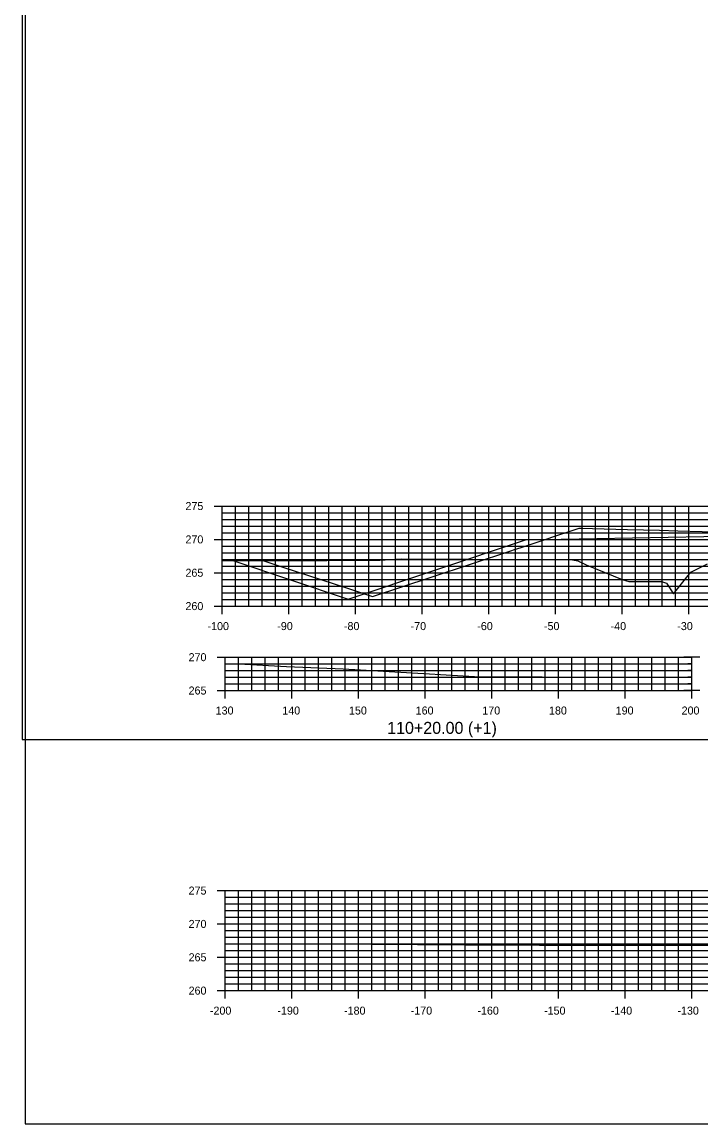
# Model space of a CAD drawing. Extents: x 1661012 to 1662122, y 670053 to 671852.
# Drawn here: x 1661677 to 1661778.9, y 671480 to 671645.2 of the extents above; entities that cross this region are included whole.
import ezdxf

# ---------------------------------------------------------------- set-up
doc = ezdxf.new("R2010")
doc.units = 0
for name, color, linetype in [('R_Concrete', 7, 'Continuous'), ('R_Concrete Hidden', 7, 'Continuous'), ('R_Erosion', 7, 'Continuous'), ('R_Exist Surface', 7, 'Continuous'), ('R_Proposed Road', 7, 'Continuous'), ('R_ROW Annot', 7, 'Continuous')]:
    doc.layers.add(name, color=color, linetype=linetype)

msp = doc.modelspace()

# ---------------------------------------------------------------- linework, layer by layer
at = {"layer": 'R_Concrete'}
for p, q in [((1661705.82, 671572.62), (1661708.22, 671572.62)), ((1661707.02, 671572.62), (1661907.02, 671572.62)), ((1661707.02, 671557.62), (1661707.02, 671572.62)), ((1661707.02, 671557.62), (1661707.02, 671572.62)), ((1661709.02, 671557.62), (1661709.02, 671572.62)), ((1661711.02, 671557.62), (1661711.02, 671572.62)), ((1661713.02, 671557.62), (1661713.02, 671572.62)), ((1661715.02, 671557.62), (1661715.02, 671572.62)), ((1661717.02, 671557.62), (1661717.02, 671572.62)), ((1661719.02, 671557.62), (1661719.02, 671572.62)), ((1661721.02, 671557.62), (1661721.02, 671572.62)), ((1661723.02, 671557.62), (1661723.02, 671572.62)), ((1661725.02, 671557.62), (1661725.02, 671572.62)), ((1661727.02, 671557.62), (1661727.02, 671572.62)), ((1661729.02, 671557.62), (1661729.02, 671572.62)), ((1661731.02, 671557.62), (1661731.02, 671572.62)), ((1661733.02, 671557.62), (1661733.02, 671572.62)), ((1661735.02, 671557.62), (1661735.02, 671572.62)), ((1661737.02, 671557.62), (1661737.02, 671572.62)), ((1661739.02, 671557.62), (1661739.02, 671572.62)), ((1661741.02, 671557.62), (1661741.02, 671572.62)), ((1661743.02, 671557.62), (1661743.02, 671572.62)), ((1661745.02, 671557.62), (1661745.02, 671572.62)), ((1661747.02, 671557.62), (1661747.02, 671572.62)), ((1661749.02, 671557.62), (1661749.02, 671572.62)), ((1661751.02, 671557.62), (1661751.02, 671572.62)), ((1661753.02, 671557.62), (1661753.02, 671572.62)), ((1661755.02, 671557.62), (1661755.02, 671572.62)), ((1661757.02, 671557.62), (1661757.02, 671572.62)), ((1661759.02, 671557.62), (1661759.02, 671572.62)), ((1661761.02, 671557.62), (1661761.02, 671572.62)), ((1661763.02, 671557.62), (1661763.02, 671572.62)), ((1661765.02, 671557.62), (1661765.02, 671572.62)), ((1661767.02, 671557.62), (1661767.02, 671572.62)), ((1661769.02, 671557.62), (1661769.02, 671572.62)), ((1661771.02, 671557.62), (1661771.02, 671572.62)), ((1661773.02, 671557.62), (1661773.02, 671572.62)), ((1661775.02, 671557.62), (1661775.02, 671572.62)), ((1661777.02, 671557.62), (1661777.02, 671572.62)), ((1661707.02, 671571.62), (1661907.02, 671571.62)), ((1661707.02, 671571.62), (1661707.62, 671571.62)), ((1661707.02, 671570.62), (1661907.02, 671570.62)), ((1661707.02, 671570.62), (1661707.62, 671570.62)), ((1661707.02, 671569.62), (1661907.02, 671569.62)), ((1661707.02, 671569.62), (1661707.62, 671569.62)), ((1661705.82, 671567.62), (1661708.22, 671567.62)), ((1661707.02, 671568.62), (1661907.02, 671568.62)), ((1661707.02, 671568.62), (1661707.62, 671568.62)), ((1661707.02, 671567.62), (1661907.02, 671567.62)), ((1661707.02, 671566.62), (1661907.02, 671566.62)), ((1661707.02, 671566.62), (1661707.62, 671566.62)), ((1661707.02, 671565.62), (1661907.02, 671565.62)), ((1661707.02, 671565.62), (1661707.62, 671565.62)), ((1661707.02, 671564.62), (1661907.02, 671564.62)), ((1661707.02, 671564.62), (1661707.62, 671564.62)), ((1661705.82, 671562.62), (1661708.22, 671562.62)), ((1661707.02, 671563.62), (1661907.02, 671563.62)), ((1661707.02, 671563.62), (1661707.62, 671563.62)), ((1661707.02, 671562.62), (1661907.02, 671562.62)), ((1661707.02, 671561.62), (1661907.02, 671561.62)), ((1661707.02, 671561.62), (1661707.62, 671561.62)), ((1661707.02, 671560.62), (1661907.02, 671560.62)), ((1661707.02, 671560.62), (1661707.62, 671560.62)), ((1661707.02, 671559.62), (1661907.02, 671559.62)), ((1661707.02, 671559.62), (1661707.62, 671559.62)), ((1661705.82, 671557.62), (1661708.22, 671557.62)), ((1661707.02, 671556.42), (1661707.02, 671558.82)), ((1661707.02, 671558.62), (1661907.02, 671558.62)), ((1661707.02, 671558.62), (1661707.62, 671558.62)), ((1661707.02, 671557.62), (1661707.02, 671558.22)), ((1661707.02, 671557.62), (1661907.02, 671557.62)), ((1661709.02, 671557.62), (1661709.02, 671558.22)), ((1661711.02, 671557.62), (1661711.02, 671558.22)), ((1661713.02, 671557.62), (1661713.02, 671558.22)), ((1661715.02, 671557.62), (1661715.02, 671558.22)), ((1661717.02, 671556.42), (1661717.02, 671558.82)), ((1661719.02, 671557.62), (1661719.02, 671558.22)), ((1661721.02, 671557.62), (1661721.02, 671558.22)), ((1661723.02, 671557.62), (1661723.02, 671558.22)), ((1661725.02, 671557.62), (1661725.02, 671558.22)), ((1661727.02, 671556.42), (1661727.02, 671558.82)), ((1661729.02, 671557.62), (1661729.02, 671558.22)), ((1661731.02, 671557.62), (1661731.02, 671558.22)), ((1661733.02, 671557.62), (1661733.02, 671558.22)), ((1661735.02, 671557.62), (1661735.02, 671558.22)), ((1661737.02, 671556.42), (1661737.02, 671558.82)), ((1661739.02, 671557.62), (1661739.02, 671558.22)), ((1661741.02, 671557.62), (1661741.02, 671558.22)), ((1661743.02, 671557.62), (1661743.02, 671558.22)), ((1661745.02, 671557.62), (1661745.02, 671558.22)), ((1661747.02, 671556.42), (1661747.02, 671558.82)), ((1661749.02, 671557.62), (1661749.02, 671558.22)), ((1661751.02, 671557.62), (1661751.02, 671558.22)), ((1661753.02, 671557.62), (1661753.02, 671558.22)), ((1661755.02, 671557.62), (1661755.02, 671558.22)), ((1661757.02, 671556.42), (1661757.02, 671558.82)), ((1661759.02, 671557.62), (1661759.02, 671558.22)), ((1661761.02, 671557.62), (1661761.02, 671558.22)), ((1661763.02, 671557.62), (1661763.02, 671558.22)), ((1661765.02, 671557.62), (1661765.02, 671558.22)), ((1661767.02, 671556.42), (1661767.02, 671558.82)), ((1661769.02, 671557.62), (1661769.02, 671558.22)), ((1661771.02, 671557.62), (1661771.02, 671558.22)), ((1661773.02, 671557.62), (1661773.02, 671558.22)), ((1661775.02, 671557.62), (1661775.02, 671558.22)), ((1661777.02, 671556.42), (1661777.02, 671558.82)), ((1661706.3, 671549.96), (1661708.7, 671549.96)), ((1661707.5, 671549.96), (1661777.5, 671549.96)), ((1661707.5, 671544.96), (1661707.5, 671549.96)), ((1661707.5, 671544.96), (1661707.5, 671549.96)), ((1661707.5, 671544.96), (1661707.5, 671549.96)), ((1661709.5, 671544.96), (1661709.5, 671549.96)), ((1661711.5, 671544.96), (1661711.5, 671549.96)), ((1661713.5, 671544.96), (1661713.5, 671549.96)), ((1661715.5, 671544.96), (1661715.5, 671549.96)), ((1661717.5, 671544.96), (1661717.5, 671549.96)), ((1661719.5, 671544.96), (1661719.5, 671549.96)), ((1661721.5, 671544.96), (1661721.5, 671549.96)), ((1661723.5, 671544.96), (1661723.5, 671549.96)), ((1661725.5, 671544.96), (1661725.5, 671549.96)), ((1661727.5, 671544.96), (1661727.5, 671549.96)), ((1661729.5, 671544.96), (1661729.5, 671549.96)), ((1661731.5, 671544.96), (1661731.5, 671549.96)), ((1661733.5, 671544.96), (1661733.5, 671549.96)), ((1661735.5, 671544.96), (1661735.5, 671549.96)), ((1661737.5, 671544.96), (1661737.5, 671549.96)), ((1661739.5, 671544.96), (1661739.5, 671549.96)), ((1661741.5, 671544.96), (1661741.5, 671549.96)), ((1661743.5, 671544.96), (1661743.5, 671549.96)), ((1661745.5, 671544.96), (1661745.5, 671549.96)), ((1661747.5, 671544.96), (1661747.5, 671549.96)), ((1661749.5, 671544.96), (1661749.5, 671549.96)), ((1661751.5, 671544.96), (1661751.5, 671549.96)), ((1661753.5, 671544.96), (1661753.5, 671549.96)), ((1661755.5, 671544.96), (1661755.5, 671549.96)), ((1661757.5, 671544.96), (1661757.5, 671549.96)), ((1661759.5, 671544.96), (1661759.5, 671549.96)), ((1661761.5, 671544.96), (1661761.5, 671549.96)), ((1661763.5, 671544.96), (1661763.5, 671549.96)), ((1661765.5, 671544.96), (1661765.5, 671549.96)), ((1661767.5, 671544.96), (1661767.5, 671549.96)), ((1661769.5, 671544.96), (1661769.5, 671549.96)), ((1661771.5, 671544.96), (1661771.5, 671549.96)), ((1661773.5, 671544.96), (1661773.5, 671549.96)), ((1661775.5, 671544.96), (1661775.5, 671549.96)), ((1661778.7, 671549.96), (1661776.3, 671549.96)), ((1661777.5, 671544.96), (1661777.5, 671549.96)), ((1661777.5, 671544.96), (1661777.5, 671549.96)), ((1661707.5, 671548.96), (1661777.5, 671548.96)), ((1661707.5, 671548.96), (1661708.1, 671548.96)), ((1661707.5, 671547.96), (1661777.5, 671547.96)), ((1661707.5, 671547.96), (1661708.1, 671547.96)), ((1661777.5, 671548.96), (1661776.9, 671548.96)), ((1661777.5, 671547.96), (1661776.9, 671547.96)), ((1661707.5, 671546.96), (1661777.5, 671546.96)), ((1661707.5, 671546.96), (1661708.1, 671546.96)), ((1661707.5, 671543.76), (1661707.5, 671546.16)), ((1661707.5, 671543.76), (1661707.5, 671546.16)), ((1661707.5, 671545.96), (1661777.5, 671545.96)), ((1661707.5, 671545.96), (1661708.1, 671545.96)), ((1661717.5, 671543.76), (1661717.5, 671546.16)), ((1661727.5, 671543.76), (1661727.5, 671546.16)), ((1661737.5, 671543.76), (1661737.5, 671546.16)), ((1661747.5, 671543.76), (1661747.5, 671546.16)), ((1661757.5, 671543.76), (1661757.5, 671546.16)), ((1661767.5, 671543.76), (1661767.5, 671546.16)), ((1661777.5, 671546.96), (1661776.9, 671546.96)), ((1661777.5, 671545.96), (1661776.9, 671545.96)), ((1661777.5, 671543.76), (1661777.5, 671546.16)), ((1661706.3, 671544.96), (1661708.7, 671544.96)), ((1661707.5, 671544.96), (1661707.5, 671545.56)), ((1661707.5, 671544.96), (1661777.5, 671544.96)), ((1661709.5, 671544.96), (1661709.5, 671545.56)), ((1661711.5, 671544.96), (1661711.5, 671545.56)), ((1661713.5, 671544.96), (1661713.5, 671545.56)), ((1661715.5, 671544.96), (1661715.5, 671545.56)), ((1661719.5, 671544.96), (1661719.5, 671545.56)), ((1661721.5, 671544.96), (1661721.5, 671545.56)), ((1661723.5, 671544.96), (1661723.5, 671545.56)), ((1661725.5, 671544.96), (1661725.5, 671545.56)), ((1661729.5, 671544.96), (1661729.5, 671545.56)), ((1661731.5, 671544.96), (1661731.5, 671545.56)), ((1661733.5, 671544.96), (1661733.5, 671545.56)), ((1661735.5, 671544.96), (1661735.5, 671545.56)), ((1661739.5, 671544.96), (1661739.5, 671545.56)), ((1661741.5, 671544.96), (1661741.5, 671545.56)), ((1661743.5, 671544.96), (1661743.5, 671545.56)), ((1661745.5, 671544.96), (1661745.5, 671545.56)), ((1661749.5, 671544.96), (1661749.5, 671545.56)), ((1661751.5, 671544.96), (1661751.5, 671545.56)), ((1661753.5, 671544.96), (1661753.5, 671545.56)), ((1661755.5, 671544.96), (1661755.5, 671545.56)), ((1661759.5, 671544.96), (1661759.5, 671545.56)), ((1661761.5, 671544.96), (1661761.5, 671545.56)), ((1661763.5, 671544.96), (1661763.5, 671545.56)), ((1661765.5, 671544.96), (1661765.5, 671545.56)), ((1661769.5, 671544.96), (1661769.5, 671545.56)), ((1661771.5, 671544.96), (1661771.5, 671545.56)), ((1661773.5, 671544.96), (1661773.5, 671545.56)), ((1661775.5, 671544.96), (1661775.5, 671545.56)), ((1661778.7, 671544.96), (1661776.3, 671544.96)), ((1661777.5, 671544.96), (1661777.5, 671545.56)), ((1661706.3, 671514.96), (1661708.7, 671514.96)), ((1661707.5, 671514.96), (1662037.5, 671514.96)), ((1661707.5, 671499.96), (1661707.5, 671514.96)), ((1661709.5, 671499.96), (1661709.5, 671514.96)), ((1661711.5, 671499.96), (1661711.5, 671514.96)), ((1661713.5, 671499.96), (1661713.5, 671514.96)), ((1661715.5, 671499.96), (1661715.5, 671514.96)), ((1661717.5, 671499.96), (1661717.5, 671514.96)), ((1661719.5, 671499.96), (1661719.5, 671514.96)), ((1661721.5, 671499.96), (1661721.5, 671514.96)), ((1661723.5, 671499.96), (1661723.5, 671514.96)), ((1661725.5, 671499.96), (1661725.5, 671514.96)), ((1661727.5, 671499.96), (1661727.5, 671514.96)), ((1661729.5, 671499.96), (1661729.5, 671514.96)), ((1661731.5, 671499.96), (1661731.5, 671514.96)), ((1661733.5, 671499.96), (1661733.5, 671514.96)), ((1661735.5, 671499.96), (1661735.5, 671514.96)), ((1661737.5, 671499.96), (1661737.5, 671514.96)), ((1661739.5, 671499.96), (1661739.5, 671514.96)), ((1661741.5, 671499.96), (1661741.5, 671514.96)), ((1661743.5, 671499.96), (1661743.5, 671514.96)), ((1661745.5, 671499.96), (1661745.5, 671514.96)), ((1661747.5, 671499.96), (1661747.5, 671514.96)), ((1661749.5, 671499.96), (1661749.5, 671514.96)), ((1661751.5, 671499.96), (1661751.5, 671514.96)), ((1661753.5, 671499.96), (1661753.5, 671514.96)), ((1661755.5, 671499.96), (1661755.5, 671514.96)), ((1661757.5, 671499.96), (1661757.5, 671514.96)), ((1661759.5, 671499.96), (1661759.5, 671514.96)), ((1661761.5, 671499.96), (1661761.5, 671514.96)), ((1661763.5, 671499.96), (1661763.5, 671514.96)), ((1661765.5, 671499.96), (1661765.5, 671514.96)), ((1661767.5, 671499.96), (1661767.5, 671514.96)), ((1661769.5, 671499.96), (1661769.5, 671514.96)), ((1661771.5, 671499.96), (1661771.5, 671514.96)), ((1661773.5, 671499.96), (1661773.5, 671514.96)), ((1661775.5, 671499.96), (1661775.5, 671514.96)), ((1661777.5, 671499.96), (1661777.5, 671514.96)), ((1661707.5, 671513.96), (1662037.5, 671513.96)), ((1661707.5, 671513.96), (1661708.1, 671513.96)), ((1661707.5, 671512.96), (1662037.5, 671512.96)), ((1661707.5, 671512.96), (1661708.1, 671512.96)), ((1661707.5, 671511.96), (1662037.5, 671511.96)), ((1661707.5, 671511.96), (1661708.1, 671511.96)), ((1661706.3, 671509.96), (1661708.7, 671509.96)), ((1661707.5, 671510.96), (1662037.5, 671510.96)), ((1661707.5, 671510.96), (1661708.1, 671510.96)), ((1661707.5, 671509.96), (1662037.5, 671509.96)), ((1661707.5, 671508.96), (1662037.5, 671508.96)), ((1661707.5, 671508.96), (1661708.1, 671508.96)), ((1661707.5, 671507.96), (1662037.5, 671507.96)), ((1661707.5, 671507.96), (1661708.1, 671507.96)), ((1661707.5, 671506.96), (1662037.5, 671506.96)), ((1661707.5, 671506.96), (1661708.1, 671506.96)), ((1661706.3, 671504.96), (1661708.7, 671504.96)), ((1661707.5, 671505.96), (1662037.5, 671505.96)), ((1661707.5, 671505.96), (1661708.1, 671505.96)), ((1661707.5, 671504.96), (1662037.5, 671504.96)), ((1661707.5, 671503.96), (1662037.5, 671503.96)), ((1661707.5, 671503.96), (1661708.1, 671503.96)), ((1661707.5, 671502.96), (1662037.5, 671502.96)), ((1661707.5, 671502.96), (1661708.1, 671502.96)), ((1661707.5, 671501.96), (1662037.5, 671501.96)), ((1661707.5, 671501.96), (1661708.1, 671501.96)), ((1661706.3, 671499.96), (1661708.7, 671499.96)), ((1661707.5, 671498.76), (1661707.5, 671501.16)), ((1661707.5, 671500.96), (1662037.5, 671500.96)), ((1661707.5, 671500.96), (1661708.1, 671500.96)), ((1661707.5, 671499.96), (1662037.5, 671499.96)), ((1661709.5, 671499.96), (1661709.5, 671500.56)), ((1661711.5, 671499.96), (1661711.5, 671500.56)), ((1661713.5, 671499.96), (1661713.5, 671500.56)), ((1661715.5, 671499.96), (1661715.5, 671500.56)), ((1661717.5, 671498.76), (1661717.5, 671501.16)), ((1661719.5, 671499.96), (1661719.5, 671500.56)), ((1661721.5, 671499.96), (1661721.5, 671500.56)), ((1661723.5, 671499.96), (1661723.5, 671500.56)), ((1661725.5, 671499.96), (1661725.5, 671500.56)), ((1661727.5, 671498.76), (1661727.5, 671501.16)), ((1661729.5, 671499.96), (1661729.5, 671500.56)), ((1661731.5, 671499.96), (1661731.5, 671500.56)), ((1661733.5, 671499.96), (1661733.5, 671500.56)), ((1661735.5, 671499.96), (1661735.5, 671500.56)), ((1661737.5, 671498.76), (1661737.5, 671501.16)), ((1661739.5, 671499.96), (1661739.5, 671500.56)), ((1661741.5, 671499.96), (1661741.5, 671500.56)), ((1661743.5, 671499.96), (1661743.5, 671500.56)), ((1661745.5, 671499.96), (1661745.5, 671500.56)), ((1661747.5, 671498.76), (1661747.5, 671501.16)), ((1661749.5, 671499.96), (1661749.5, 671500.56)), ((1661751.5, 671499.96), (1661751.5, 671500.56)), ((1661753.5, 671499.96), (1661753.5, 671500.56)), ((1661755.5, 671499.96), (1661755.5, 671500.56)), ((1661757.5, 671498.76), (1661757.5, 671501.16)), ((1661759.5, 671499.96), (1661759.5, 671500.56)), ((1661761.5, 671499.96), (1661761.5, 671500.56)), ((1661763.5, 671499.96), (1661763.5, 671500.56)), ((1661765.5, 671499.96), (1661765.5, 671500.56)), ((1661767.5, 671498.76), (1661767.5, 671501.16)), ((1661769.5, 671499.96), (1661769.5, 671500.56)), ((1661771.5, 671499.96), (1661771.5, 671500.56)), ((1661773.5, 671499.96), (1661773.5, 671500.56)), ((1661775.5, 671499.96), (1661775.5, 671500.56)), ((1661777.5, 671498.76), (1661777.5, 671501.16))]:
    msp.add_line(p, q, dxfattribs=at)
at = {"layer": 'R_Erosion'}
for points in [[(1661707.02, 671564.46), (1661714.02, 671564.46), (1661722.72, 671564.47), (1661730.71, 671564.52), (1661733.9, 671564.7), (1661754.7, 671564.6), (1661759.31, 671564.6), (1661760.4, 671564.4), (1661761.64, 671563.8), (1661767.03, 671561.61), (1661768.02, 671561.29), (1661772.95, 671561.3), (1661773.71, 671561.06), (1661774.72, 671559.47), (1661777.32, 671562.7), (1661779.85, 671563.96)], [(1661707.5, 671549.02), (1661709.53, 671548.95), (1661716.7, 671548.57), (1661725.18, 671548.22), (1661738.13, 671547.45), (1661739.8, 671547.34), (1661745.75, 671546.99), (1661755.06, 671547.01), (1661765.14, 671546.95), (1661769.02, 671546.94), (1661777.5, 671546.9)], [(1661729.53, 671506.93), (1661732.1, 671506.91), (1661736.35, 671506.88), (1661743.54, 671506.84), (1661747.89, 671506.81), (1661754.66, 671506.76), (1661762.37, 671506.78), (1661765.51, 671506.79), (1661767.07, 671506.79), (1661782.62, 671506.79)]]:
    msp.add_lwpolyline(points, dxfattribs=at)
at = {"layer": 'R_Exist Surface'}
for p, q in [((1661707.02, 671557.62), (1661707.02, 671572.62)), ((1661707.02, 671557.62), (1661907.02, 671557.62)), ((1661707.5, 671544.96), (1661707.5, 671549.96)), ((1661777.5, 671544.96), (1661777.5, 671549.96)), ((1661707.5, 671544.96), (1661777.5, 671544.96)), ((1661707.5, 671499.96), (1661707.5, 671514.96)), ((1661707.5, 671499.96), (1662037.5, 671499.96))]:
    msp.add_line(p, q, dxfattribs=at)
at = {"layer": 'R_Proposed Road'}
for points in [[(1661677.02, 671537.62), (1662037.02, 671537.62), (1662037.02, 671730.32), (1661677.02, 671730.32)], [(1661677.5, 671479.96), (1662037.5, 671479.96), (1662037.5, 671672.66), (1661677.5, 671672.66)]]:
    msp.add_lwpolyline(points, close=True, dxfattribs=at)
at = {"layer": 'R_ROW Annot'}
for points in [[(1661713.15, 671564.46), (1661715.68, 671563.63), (1661716.16, 671563.47), (1661725.67, 671560.34), (1661729.58, 671559.06), (1661738.41, 671561.98), (1661750.51, 671565.98), (1661750.74, 671566.05), (1661751.89, 671566.43), (1661755.94, 671567.77), (1661756.65, 671568.01), (1661759.68, 671569.01), (1661760.58, 671569.3), (1661761.13, 671569.3), (1661762.59, 671569.28), (1661767.86, 671569.13), (1661772.65, 671569), (1661775.41, 671568.92), (1661782.71, 671568.73)], [(1661708.63, 671564.46), (1661725.96, 671558.68), (1661752.52, 671567.54), (1661784.62, 671568.18), (1661792.02, 671568.33), (1661796.02, 671568.49), (1661807.02, 671568.71), (1661818.02, 671568.49), (1661822.02, 671568.33), (1661829.43, 671567.1), (1661830.02, 671567), (1661846.15, 671561.62)]]:
    msp.add_lwpolyline(points, dxfattribs=at)

# ---------------------------------------------------------------- texts
at = {"layer": 'R_Concrete Hidden'}
for s, height, p in [('275', 1.2, (1661701.54, 671572.02)), ('270', 1.2, (1661701.54, 671567.02)), ('265', 1.2, (1661701.54, 671562.02)), ('260', 1.2, (1661701.54, 671557.02)), ('-100', 1.2, (1661704.85, 671554.02)), ('-90', 1.2, (1661715.31, 671554.02)), ('-80', 1.2, (1661725.31, 671554.02)), ('-70', 1.2, (1661735.31, 671554.02)), ('-60', 1.2, (1661745.31, 671554.02)), ('-50', 1.2, (1661755.31, 671554.02)), ('-40', 1.2, (1661765.31, 671554.02)), ('-30', 1.2, (1661775.31, 671554.02)), ('270', 1.2, (1661702.01, 671549.36)), ('265', 1.2, (1661702.01, 671544.36)), ('130', 1.2, (1661706.07, 671541.36)), ('130', 1.2, (1661706.07, 671541.36)), ('140', 1.2, (1661716.07, 671541.36)), ('150', 1.2, (1661726.07, 671541.36)), ('160', 1.2, (1661736.07, 671541.36)), ('170', 1.2, (1661746.07, 671541.36)), ('180', 1.2, (1661756.07, 671541.36)), ('190', 1.2, (1661766.07, 671541.36)), ('200', 1.2, (1661775.96, 671541.36)), ('110+20.00 (+1)', 1.8, (1661731.79, 671538.46)), ('275', 1.2, (1661702.01, 671514.36)), ('270', 1.2, (1661702.01, 671509.36)), ('265', 1.2, (1661702.01, 671504.36)), ('260', 1.2, (1661702.01, 671499.36)), ('-200', 1.2, (1661705.21, 671496.36)), ('-190', 1.2, (1661715.33, 671496.36)), ('-180', 1.2, (1661725.33, 671496.36)), ('-170', 1.2, (1661735.33, 671496.36)), ('-160', 1.2, (1661745.33, 671496.36)), ('-150', 1.2, (1661755.33, 671496.36)), ('-140', 1.2, (1661765.33, 671496.36)), ('-130', 1.2, (1661775.33, 671496.36))]:
    msp.add_text(s, height=height, dxfattribs=at).set_placement(p)
at = {"layer": 'R_Exist Surface'}
for p in [(1661707.02, 671557.62), (1661707.5, 671544.96), (1661707.5, 671499.96)]:
    msp.add_text('-', height=0.0001, dxfattribs=at).set_placement(p)

doc.saveas('drawing.dxf')
